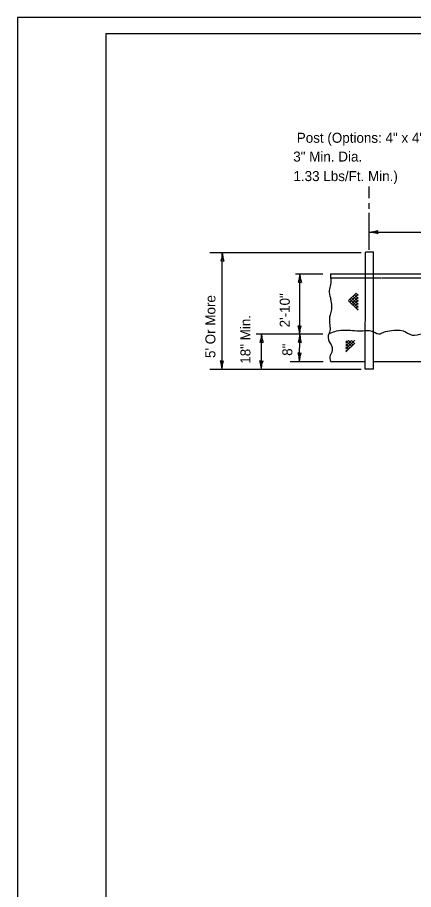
# Model space of a CAD drawing. Extents: x 539344 to 540004, y 1574686 to 1575110.
# Drawn here: x 539344 to 539442.7, y 1574893 to 1575110.5 of the extents above; entities that cross this region are included whole.
import ezdxf

# ---------------------------------------------------------------- set-up
doc = ezdxf.new("R2010")
doc.units = 0
for name, color, linetype in [('Default', 7, 'Continuous'), ('PlotBorder_dp', 7, 'Continuous'), ('SheetBorder_dp', 7, 'Continuous')]:
    doc.layers.add(name, color=color, linetype=linetype)

msp = doc.modelspace()

# ---------------------------------------------------------------- linework, layer by layer
at = {"layer": 'Default'}
for p, q in [((539431.6, 1575056.95), (539492.34, 1575056.95)), ((539433.66, 1575056.94), (539433.74, 1575057.32)), ((539433.66, 1575056.94), (539433.74, 1575056.55)), ((539430.65, 1575051.98), (539432.66, 1575051.99)), ((539432.66, 1575046.54), (539432.66, 1575051.99)), ((539391.92, 1575051.85), (539429.61, 1575051.88)), ((539394.98, 1575049.8), (539394.6, 1575049.72)), ((539394.93, 1575022.72), (539395, 1575051.86)), ((539394.98, 1575049.8), (539395.37, 1575049.72)), ((539430.68, 1575046.54), (539430.68, 1575051.89)), ((539413.22, 1575046.54), (539420.08, 1575046.54)), ((539414.28, 1575031.46), (539414.32, 1575046.54)), ((539421.99, 1575046.54), (539434.49, 1575046.54)), ((539422, 1575045.55), (539434.49, 1575045.56)), ((539430.63, 1575022.75), (539430.68, 1575046.54)), ((539432.66, 1575022.75), (539432.66, 1575046.81)), ((539434.49, 1575046.52), (539456.95, 1575046.53)), ((539434.67, 1575045.56), (539457.13, 1575045.55)), ((539414.3, 1575044.49), (539413.92, 1575044.41)), ((539414.3, 1575044.49), (539414.69, 1575044.41)), ((539428.35, 1575041.74), (539426.48, 1575039.87)), ((539428.84, 1575041.49), (539426.81, 1575039.46)), ((539427.92, 1575041.32), (539428.84, 1575040.4)), ((539428.3, 1575041.69), (539428.84, 1575041.14)), ((539426.48, 1575039.79), (539428.84, 1575037.43)), ((539426.81, 1575040.2), (539428.84, 1575038.17)), ((539428.84, 1575040.75), (539427.18, 1575039.09)), ((539427.18, 1575040.57), (539428.84, 1575038.91)), ((539427.55, 1575040.95), (539428.84, 1575039.66)), ((539428.84, 1575040.01), (539427.55, 1575038.72)), ((539428.84, 1575039.26), (539427.92, 1575038.35)), ((539428.84, 1575038.52), (539428.3, 1575037.98)), ((539428.84, 1575037.78), (539428.67, 1575037.6)), ((539414.29, 1575033.52), (539413.91, 1575033.59)), ((539414.29, 1575033.52), (539414.68, 1575033.59)), ((539403.42, 1575031.56), (539420.07, 1575031.55)), ((539404.74, 1575022.72), (539404.76, 1575031.56)), ((539414.26, 1575024.69), (539414.28, 1575031.55)), ((539421.87, 1575031.71), (539421.53, 1575031.52)), ((539404.74, 1575029.5), (539404.36, 1575029.43)), ((539404.74, 1575029.5), (539405.13, 1575029.43)), ((539414.27, 1575029.5), (539413.88, 1575029.42)), ((539414.27, 1575029.5), (539414.65, 1575029.42)), ((539426.48, 1575029.94), (539425.82, 1575029.28)), ((539427.22, 1575029.94), (539425.82, 1575028.53)), ((539427.97, 1575029.94), (539425.82, 1575027.79)), ((539425.82, 1575029.81), (539427.17, 1575028.46)), ((539428.05, 1575029.28), (539425.82, 1575027.05)), ((539425.82, 1575029.07), (539426.8, 1575028.09)), ((539425.82, 1575028.33), (539426.43, 1575027.72)), ((539426.43, 1575029.94), (539427.54, 1575028.83)), ((539427.18, 1575029.94), (539427.91, 1575029.2)), ((539427.92, 1575029.94), (539428.05, 1575029.81)), ((539414.28, 1575026.75), (539413.89, 1575026.83)), ((539414.28, 1575026.75), (539414.66, 1575026.82)), ((539425.82, 1575027.58), (539426.06, 1575027.34)), ((539394.94, 1575024.78), (539394.56, 1575024.86)), ((539394.94, 1575024.78), (539395.33, 1575024.85)), ((539404.75, 1575024.78), (539404.37, 1575024.86)), ((539404.75, 1575024.78), (539405.14, 1575024.86)), ((539411.93, 1575024.68), (539420.09, 1575024.71)), ((539421.92, 1575024.67), (539430.63, 1575024.67)), ((539432.66, 1575024.67), (539491.35, 1575024.67)), ((539391.93, 1575022.72), (539429.63, 1575022.73)), ((539432.66, 1575022.75), (539430.63, 1575022.75))]:
    msp.add_line(p, q, dxfattribs=at)
for points in [[(539431.6, 1575065.37), (539431.6, 1575068.33)], [(539431.6, 1575062.73), (539431.6, 1575064.17)], [(539431.6, 1575052.54), (539431.6, 1575061.71)], [(539431.6, 1575056.95), (539432.7, 1575057.07), (539433.16, 1575057.18), (539433.74, 1575057.35)], [(539431.6, 1575056.95), (539432.7, 1575056.83), (539433.16, 1575056.72), (539433.74, 1575056.55)], [(539432.48, 1575056.95), (539432.77, 1575056.97), (539432.95, 1575057.01), (539433.1, 1575057.02), (539433.22, 1575057.06), (539433.4, 1575057.1), (539433.37, 1575056.95), (539433.4, 1575056.78), (539433.26, 1575056.84), (539433.15, 1575056.87), (539433.03, 1575056.89), (539432.91, 1575056.91), (539432.81, 1575056.92), (539432.69, 1575056.94), (539432.48, 1575056.95)], [(539395, 1575051.86), (539394.87, 1575050.76), (539394.76, 1575050.3), (539394.6, 1575049.72)], [(539395, 1575050.98), (539395.02, 1575050.69), (539395.05, 1575050.51), (539395.07, 1575050.36), (539395.11, 1575050.24), (539395.15, 1575050.06), (539394.99, 1575050.09), (539394.83, 1575050.06), (539394.89, 1575050.2), (539394.92, 1575050.31), (539394.93, 1575050.43), (539394.96, 1575050.55), (539394.97, 1575050.65), (539394.99, 1575050.77), (539395, 1575050.98)], [(539395, 1575051.86), (539395.11, 1575050.76), (539395.23, 1575050.3), (539395.4, 1575049.72)], [(539414.32, 1575046.54), (539414.19, 1575045.45), (539414.08, 1575044.98), (539413.92, 1575044.41)], [(539414.31, 1575045.67), (539414.34, 1575045.38), (539414.37, 1575045.2), (539414.39, 1575045.04), (539414.42, 1575044.92), (539414.47, 1575044.74), (539414.31, 1575044.78), (539414.15, 1575044.74), (539414.21, 1575044.89), (539414.23, 1575045), (539414.25, 1575045.12), (539414.28, 1575045.23), (539414.29, 1575045.33), (539414.3, 1575045.45), (539414.31, 1575045.67)], [(539414.32, 1575046.54), (539414.43, 1575045.45), (539414.54, 1575044.98), (539414.71, 1575044.41)], [(539414.28, 1575031.46), (539414.16, 1575032.56), (539414.05, 1575033.02), (539413.88, 1575033.59)], [(539414.28, 1575032.33), (539414.26, 1575032.62), (539414.22, 1575032.81), (539414.21, 1575032.96), (539414.17, 1575033.08), (539414.13, 1575033.26), (539414.28, 1575033.23), (539414.45, 1575033.26), (539414.39, 1575033.11), (539414.36, 1575033), (539414.34, 1575032.88), (539414.32, 1575032.77), (539414.31, 1575032.67), (539414.29, 1575032.55), (539414.28, 1575032.33)], [(539414.28, 1575031.46), (539414.4, 1575032.56), (539414.52, 1575033.02), (539414.68, 1575033.59)], [(539404.76, 1575031.56), (539404.64, 1575030.46), (539404.52, 1575030), (539404.36, 1575029.43)], [(539404.76, 1575030.69), (539404.78, 1575030.4), (539404.82, 1575030.22), (539404.83, 1575030.06), (539404.87, 1575029.94), (539404.91, 1575029.76), (539404.75, 1575029.8), (539404.59, 1575029.76), (539404.65, 1575029.91), (539404.68, 1575030.02), (539404.7, 1575030.14), (539404.72, 1575030.25), (539404.73, 1575030.35), (539404.75, 1575030.47), (539404.76, 1575030.69)], [(539404.76, 1575031.56), (539404.88, 1575030.46), (539404.99, 1575030), (539405.16, 1575029.43)], [(539414.28, 1575031.55), (539414.16, 1575030.46), (539414.04, 1575029.99), (539413.88, 1575029.42)], [(539414.28, 1575030.68), (539414.3, 1575030.39), (539414.34, 1575030.21), (539414.35, 1575030.05), (539414.39, 1575029.93), (539414.43, 1575029.75), (539414.28, 1575029.79), (539414.11, 1575029.75), (539414.17, 1575029.9), (539414.2, 1575030.01), (539414.22, 1575030.13), (539414.24, 1575030.24), (539414.25, 1575030.34), (539414.27, 1575030.47), (539414.28, 1575030.68)], [(539414.28, 1575031.55), (539414.4, 1575030.46), (539414.51, 1575029.99), (539414.68, 1575029.42)], [(539414.26, 1575024.69), (539414.15, 1575025.79), (539414.04, 1575026.25), (539413.87, 1575026.83)], [(539414.27, 1575025.56), (539414.24, 1575025.86), (539414.21, 1575026.04), (539414.19, 1575026.19), (539414.16, 1575026.31), (539414.11, 1575026.49), (539414.27, 1575026.46), (539414.43, 1575026.49), (539414.37, 1575026.34), (539414.34, 1575026.23), (539414.33, 1575026.11), (539414.3, 1575026), (539414.29, 1575025.9), (539414.28, 1575025.78), (539414.27, 1575025.56)], [(539414.26, 1575024.69), (539414.39, 1575025.79), (539414.5, 1575026.25), (539414.66, 1575026.82)], [(539394.93, 1575022.72), (539394.81, 1575023.82), (539394.7, 1575024.28), (539394.53, 1575024.86)], [(539394.93, 1575023.6), (539394.91, 1575023.89), (539394.87, 1575024.07), (539394.85, 1575024.22), (539394.82, 1575024.34), (539394.78, 1575024.52), (539394.93, 1575024.49), (539395.09, 1575024.52), (539395.03, 1575024.38), (539395.01, 1575024.26), (539394.99, 1575024.14), (539394.97, 1575024.03), (539394.96, 1575023.93), (539394.94, 1575023.81), (539394.93, 1575023.6)], [(539394.93, 1575022.72), (539395.05, 1575023.82), (539395.16, 1575024.28), (539395.33, 1575024.85)], [(539404.74, 1575022.72), (539404.62, 1575023.82), (539404.51, 1575024.28), (539404.34, 1575024.86)], [(539404.74, 1575023.6), (539404.72, 1575023.89), (539404.68, 1575024.07), (539404.66, 1575024.22), (539404.63, 1575024.34), (539404.59, 1575024.52), (539404.74, 1575024.49), (539404.9, 1575024.52), (539404.84, 1575024.38), (539404.82, 1575024.27), (539404.8, 1575024.15), (539404.78, 1575024.03), (539404.77, 1575023.93), (539404.75, 1575023.81), (539404.74, 1575023.6)], [(539404.74, 1575022.72), (539404.86, 1575023.82), (539404.97, 1575024.28), (539405.14, 1575024.86)]]:
    msp.add_lwpolyline(points, dxfattribs=at)
for points in [[(539421.99, 1575046.54), (539422, 1575045.34), (539421.99, 1575043.85), (539421.63, 1575042.38), (539421.92, 1575040.53), (539422.11, 1575039.42), (539422.2, 1575037.65), (539421.86, 1575036.34), (539421.76, 1575033.74), (539421.81, 1575032.31), (539421.39, 1575031.14), (539421.92, 1575029.07), (539422.23, 1575028.62), (539422.04, 1575026.51), (539421.86, 1575026.16), (539421.92, 1575024.67)], [(539421.87, 1575031.71), (539423.49, 1575032.29), (539425.59, 1575032.48), (539427.41, 1575032.42), (539429.61, 1575032.31), (539431.37, 1575032.43), (539432.62, 1575032.09), (539434.4, 1575031.61), (539434.49, 1575031.65)], [(539434.49, 1575031.65), (539435.24, 1575031.98), (539437.12, 1575032.37), (539440.04, 1575032.33), (539442.31, 1575031.27), (539444.85, 1575031.64), (539448.03, 1575031.65), (539451.74, 1575031.35), (539455.28, 1575031.97), (539456.95, 1575032)]]:
    msp.add_spline(points, degree=3, dxfattribs=at)
at = {"layer": 'PlotBorder_dp'}
msp.add_lwpolyline([(539343.95, 1574686.45), (540003.95, 1574686.45), (540003.95, 1575110.45), (539343.95, 1575110.45)], close=True, dxfattribs=at)
at = {"layer": 'SheetBorder_dp'}
for q in [(539365.95, 1574690.45), (539981.95, 1575106.45)]:
    msp.add_line((539365.95, 1575106.45), q, dxfattribs=at)

# ---------------------------------------------------------------- texts
at = {"layer": 'Default'}
for s, p in [('Post (Options: 4" x 4" Or', (539413.56, 1575079.2)), ('3" Min. Dia.', (539412.68, 1575074.52)), ('1.33 Lbs/Ft. Min.)', (539412.73, 1575069.65))]:
    msp.add_text(s, height=2.5, dxfattribs=at).set_placement(p)
for s, p in [("5' Or More", (539393.28, 1575025.54)), ('2\'-10"', (539411.81, 1575033.18)), ('18" Min.', (539402.01, 1575024.11)), ('8"', (539412.45, 1575026.09))]:
    msp.add_text(s, height=2.5, rotation=90, dxfattribs=at).set_placement(p)

doc.saveas('drawing.dxf')
